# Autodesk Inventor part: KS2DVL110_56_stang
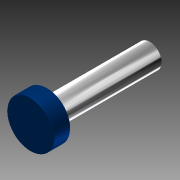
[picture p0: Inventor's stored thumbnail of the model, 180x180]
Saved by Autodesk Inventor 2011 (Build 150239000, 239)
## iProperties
Created: 2010-10
Document SubType Name: Modeling
Designer: TB
Mass: 161.233 g
Surface Area: 236.814 cm^2
Volume: 161.233 cm^3
Density: 1 g/cm^3
Author: TB
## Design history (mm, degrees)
sketch "Sketch2"
  geometry: L1 (-35, -3)-(-35, 3) reference; L2 (-35, -9)-(-35, 9) reference; L3 (-35, 28)-(-316, 28); L4 (-316, 28)-(-316, 0); L5 (-316, 0)-(-35, 0); L6 (-35, 0)-(-35, 28); L7 (-316, 28)-(-276, 28); L8 (-276, 28)-(-276, 55); L9 (-276, 55)-(-316, 55); L10 (-316, 55)-(-316, 28); 1 further point
  constraints: 16 end point, 4 parallel, 2 horizontal, 2 perpendicular, 1 midpoint
  dimensions: "Dia" = 56 diameter of L3 L5; "d3" = 281 distance of L3.start L3.end (computed from Slaglengde, Forlengelse_rør); "StempelDia" = 110 diameter of L9 L5; "StempelLengde" = 40 distance of L8.end L9.end
revolve "Revolution1" sketch "Sketch2" stored, may be unused: angle "d6" = 90 deg
fillet "Fillet1" dims "d7" = 2
sketch "Sketch3"
  geometry: L1 (-316, -53)-(-316, 53) reference; L2 (-316, 0)-(-316.01, 0); L3 (-316, 0)-(-316, 0.01); A1 r 0.01 centre (-316, 0) between (-316, 0.01) and (-316.01, 0); 1 further point
  constraints: 4 end point, 2 point on circle, 1 centre point, 1 midpoint, 1 perpendicular, 1 point on line
  dimensions: "d8" = 0.01 distance of L2.start L2.end; "d9" = 0.01 distance of L2.start L3.end (= d8); "d10" = 0.01 radius of A1 (= d8)
revolve "Revolution2" sketch "Sketch3" stored, may be unused: angle "d11" = 90 deg
body "Solid1"
node "Projected Loop2"
other parameters: "Forlengelse_rør" = 0
